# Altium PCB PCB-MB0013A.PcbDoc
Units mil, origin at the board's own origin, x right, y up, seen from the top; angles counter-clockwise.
Board outline 1190.03 x 715.03 mil, 2 copper layers (Top Layer, Bottom Layer); 10 components, 22 nets, 65 pads, 2 vias.
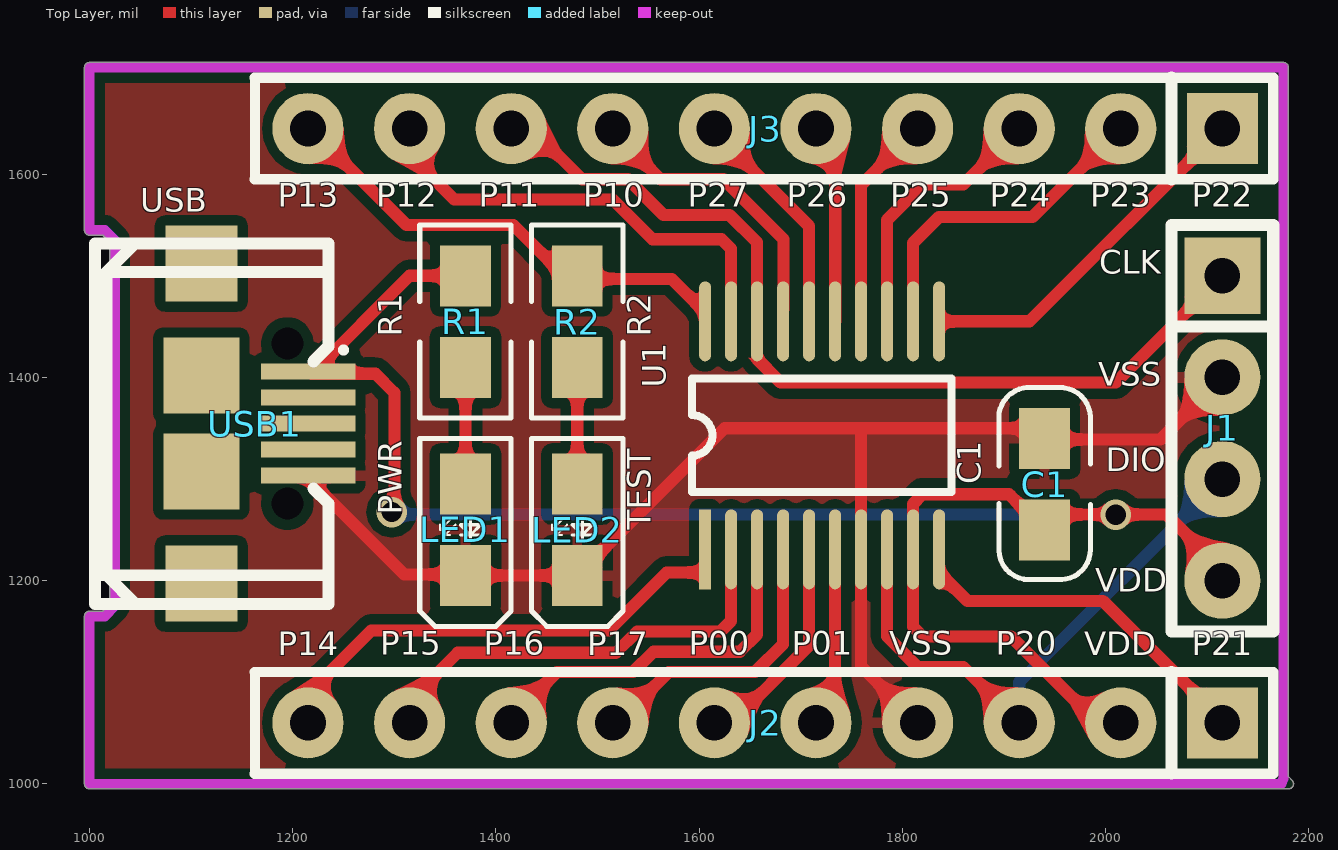
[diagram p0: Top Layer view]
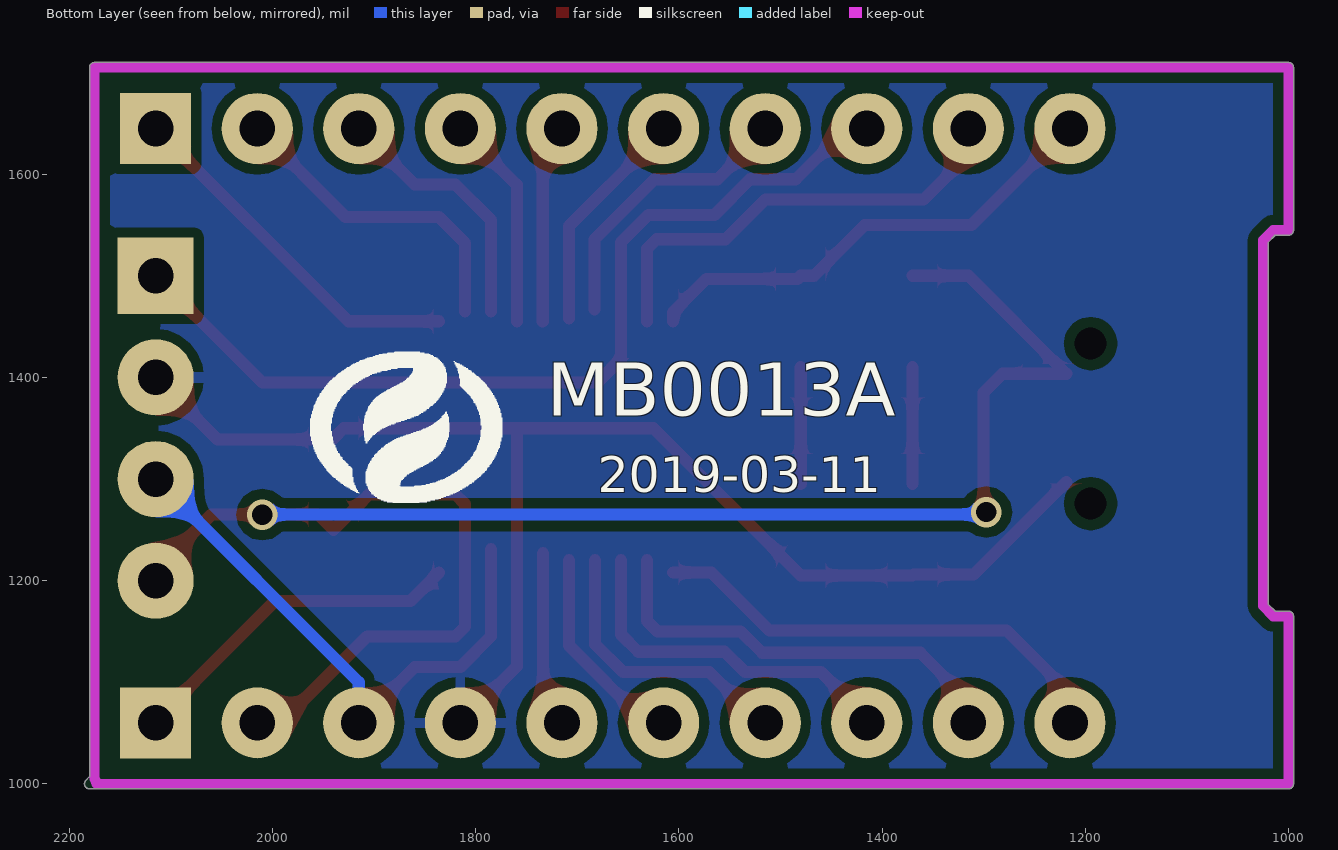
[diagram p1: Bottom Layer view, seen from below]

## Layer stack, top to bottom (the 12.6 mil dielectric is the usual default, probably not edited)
Top Solder: solder mask 0.4, Solder Resist, Dk 3.5
Top Layer: signal copper 1.4
Dielectric1: dielectric 12.6, FR-4, Dk 4.8
Bottom Layer: signal copper 1.4
Bottom Solder: solder mask 0.4, Solder Resist, Dk 3.5

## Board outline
1000,994.99 cw(c1000,1000) 994.99,1000 994.99,1165 cw(c1000,1165) 1000,1170.02 1012.92,1170.02 1019.99,1177.08 1019.99,1532.92 1012.92,1539.98 1000,1539.98 cw(c1000,1545) 994.99,1545 994.99,1705 cw(c1000,1705) 1000,1710.02 2175,1710.02 cw(c2175,1705) 2180.01,1705 2180.01,1007.08 2183.55,1003.55 2183.53,1003.56 cw(c2180,1000) 2185.01,1000 cw(c2180,1000) 2180,994.99

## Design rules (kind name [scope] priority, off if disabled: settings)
Clearance Clearance_2 [(InNamedPolygon('Top Layer-VSS'))] p1: gap=10 ignorepadtopadclearanceinfootprint=FALSE
Clearance Clearance_1 [(InNamedPolygon('Bottom Layer-VSS'))] p2: gap=10 ignorepadtopadclearanceinfootprint=FALSE
Clearance [(InComponent('USB1') AND InPadClass('All Pads')) vs (InPadClass('All Pads'))] p3: gap=1 ignorepadtopadclearanceinfootprint=FALSE except(0: Arc-Hole Track-Hole SMDPad-Hole THPad-Hole Via-Hole Fill-Hole Poly-Hole Region-Hole Text-Hole)
ComponentClearance [All] p1: gap=3 collisioncheckmode=3 verticalgap=3 showdistances=FALSE
FabricationTestpoint [(IsPad And (OnTopLayer Or OnBottomLayer))] p1: side=3 testpointundercomponent=TRUE minsize=40 maxsize=100 preferedsize=60 minholesize=0 maxholesize=40 preferedholesize=32 testpointgrid=1 allowsidetop=TRUE allowsidebottom=TRUE usegrid=TRUE gridtolerance=0.01
PolygonConnect [All] p1: connectstyle=Relief reliefconductorwidth=10 reliefentries=4 polygonreliefangle="90 Angle" airgapwidth=10
RoutingVias [All] p1: holewidth=20 width=30 viastyle="Through Hole" minholewidth=20 minwidth=30 maxholewidth=28 maxwidth=50
SolderMaskExpansion [All] p1: expansion=4
Width [All] p1: maxlimit=15 minlimit=3 preferedwidth=12
28 further rules are at their usual default settings.

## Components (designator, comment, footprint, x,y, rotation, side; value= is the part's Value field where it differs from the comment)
C1 "104" C0805 1940,1250 r90 top
J1 "烧录接口" CON1*4(P=2.54) 2115,1350 r270 top
J2 "CON1*10" CON1*10(P=2.54) 1665,1060 r180 top
J3 "CON1*10" CON1*10(P=2.54) 1665,1645 r180 top
LED1 "POWER" LED0805 1370,1250 r270 top
LED2 "TEST" LED0805 1480,1250 r270 top
R1 "1K" R0805 1370,1410 r90 top
R2 "1K" R0805 1480,1500 r270 top
U1 "SC92F8003" TSSOP20s 1721,1343 r90 top locked
USB1 "MicroUSB 供电口" microusb 1215.32,1405.7 r180 top

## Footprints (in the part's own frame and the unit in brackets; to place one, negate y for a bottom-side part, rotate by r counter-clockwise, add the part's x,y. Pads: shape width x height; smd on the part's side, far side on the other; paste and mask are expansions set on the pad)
C0805 [mil]
  rect 60x50 smd: 1(0,0) 2(90,0)
  silkscreen extent -49,-45 140,45
CON1*4(P=2.54) [mil]
  rect 75x75 hole 35: 1(-150,0)
  round 75 hole 35: 2(-50,0) 3(50,0) 4(150,0)
  silkscreen extent -200,-50 200,50
CON1*10(P=2.54) [mil]
  rect 70x70 hole 35: 1(-450,0)
  round 70 hole 35: 2(-350,0) 3(-250,0) 4(-150,0) 5(-50,0) 6(50,0) 7(150,0) 8(250,0) 9(350,0) 10(450,0)
  silkscreen extent -500,-50 502,50
LED0805 [mil]
  rect 60x50 smd: 1(-45,0) 2(45,0)
  silkscreen extent -90,-45 95,45
microusb [mm] "Connector; USB1.1, Type B, SM; 4 Position; Right Angle"
  rect 2.366x0.4 smd mask+0.001: 1(0,0) 2(0,0.65) 3(0,1.3) 4(0,1.95) 5(0,2.6)
  rect 1.8x1.9 smd: 6(2.675,-2.7) 9(2.675,5.3)
  rect 1.9x1.9 smd: 7(2.675,0.1) 8(2.675,2.5)
  round 0 hole 0.8 unplated mask+0.001: MH1(0.525,3.3) MH2(0.525,-0.7)
  silkscreen extent -0.89,-3.21 5.33,5.81, body extent -0.11,-3.09 5.52,5.71, height 2.79
R0805 [mil]
  rect 60x50 smd: 1(0,0) 2(90,0)
  silkscreen extent -50,-45 140,45
TSSOP20s [mm]
  rect 2x0.3 smd: 1(-2.85,2.925)
  oval 2x0.3 smd: 2(-2.85,2.275) 3(-2.85,1.625) 4(-2.85,0.975) 5(-2.85,0.325) 6(-2.85,-0.325) 7(-2.85,-0.975) 8(-2.85,-1.625) 9(-2.85,-2.275) 10(-2.85,-2.925) 11(2.85,-2.925) 12(2.85,-2.275) 13(2.85,-1.625) 14(2.85,-0.975) 15(2.85,-0.325) 16(2.85,0.325) 17(2.85,0.975) 18(2.85,1.625) 19(2.85,2.275) 20(2.85,2.925)
  silkscreen extent -1.41,-3.24 1.41,3.25

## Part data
C1: library part CAP1, "贴片电容"
J1: library part CON1*4
LED1 LED2: library part LED
R1 R2: library part R0805
U1: "电压:2.4V-5.5V;ROM:16KB;RAM:256B+256B;16/8/4/1.33MHz"
USB1: library part MicroUSB

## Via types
v1: diameter 30, hole 20, Top Layer to Bottom Layer, tented both sides, 2 vias

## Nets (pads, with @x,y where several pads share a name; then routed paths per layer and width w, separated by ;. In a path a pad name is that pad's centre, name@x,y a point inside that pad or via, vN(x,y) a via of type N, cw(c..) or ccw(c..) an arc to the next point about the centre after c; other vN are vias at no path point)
CLK: J1.1 J3.8 U1.18 | length 914.4
  Top Layer w12: J3.8 1435,1645 1485,1595 1530,1595 1565,1560 1630,1560 1656.87,1533.13 1656.87,1418.13 1680,1395 2010,1395 J1.1
DIO: J1.3 J2.3 U1.8 | length 573.9
  Top Layer w12: U1.8@1784.82,1230.8 1784.82,1145.18 1815,1115 1860,1115 J2.3
  Bottom Layer w12: J2.3 1915,1100 J1.3
NetLED1_1: LED1.1 R1.1 | length 115
  Top Layer w12: LED1.1 R1.1
NetLED2_1: LED2.1 R2.2 | length 115
  Top Layer w12: LED2.1 R2.2
P00: J2.6 U1.5 | length 208.5
  Top Layer w12: J2.6 1632,1060 1708.05,1136.05 U1.5@1708.05,1220
P01: J2.5 U1.6 | length 174.7
  Top Layer w12: J2.5 1733.64,1078.64 U1.6@1733.64,1227
P10: J3.7 U1.17 | length 265.4
  Top Layer w12: J3.7@1526,1631 1562,1595 1624,1595 1683,1536 U1.17@1683,1467
P12: J3.9 U1.19 | length 440.2
  Top Layer w12: J3.9@1305,1629 1359,1575 1515,1575 1554,1536 1622,1536 1631.28,1526.72 U1.19@1631.28,1455.2
P13: J3.10 R2.1 U1.20 | length 474.7
  Top Layer w12: J3.10 1217,1645 1312,1550 1417,1550 1467,1500 R2.1 1483,1497 1573,1497 1605.84,1464.16 U1.20
P14: J2.10 U1.1 | length 468.8
  Top Layer w12: J2.10 1215,1088.72 1277.28,1151 1511,1151 1568,1208 U1.1@1605.68,1208
P15: J2.9 U1.2 | length 430.2
  Top Layer w12: J2.9 1315,1081.64 1362.36,1129 1518,1129 1539,1150 1621,1150 1631.28,1160.28 U1.2@1631.28,1220
P16: J2.8 U1.3 | length 353.9
  Top Layer w12: J2.8 1415,1065 1460,1110 1535,1110 1555,1130 1640,1130 1656.87,1146.87 U1.3@1656.87,1220
P17: J2.7 U1.4 | length 260.1
  Top Layer w12: J2.7@1532,1072 1570,1110 1655,1110 1682.46,1137.46 U1.4@1682.46,1220
P21: J2.1 U1.10 | length 341.7
  Top Layer w12: U1.10@1836,1208 1864,1180 1997.36,1180 2115,1062.36 J2.1
P22: J3.1 U1.11 | length 357.5
  Top Layer w12: U1.11 1925.2,1455.2 J3.1
P23: J3.2 U1.12 | length 318.6
  Top Layer w12: U1.12@1810.41,1465 1810.41,1532.41 1836,1558 1928,1558 J3.2
P24: J3.3 U1.13 | length 257.3
  Top Layer w12: U1.13@1785,1465 1785,1555 1820,1590 1860,1590 J3.3
P25: J3.4 U1.14 | length 213.3
  Top Layer w12: U1.14@1759.23,1455.2 1759.23,1590 1760,1590 J3.4
P26: J3.5 U1.15 | length 197.7
  Top Layer w12: J3.5 1734,1626 U1.15@1734,1455.2
P27: J3.6 U1.16 | length 230
  Top Layer w12: J3.6@1603,1631 1626,1631 1708.05,1548.95 U1.16@1708.05,1458
VDD: C1.1 J1.4 J2.2 R1.2 U1.9 USB1.1 | length 1839
  Top Layer w12: v1(1297.5,1267.5) 1300,1270 1300,1385 1281.33,1403.67 1218.67,1403.67 1315,1500 R1.2 ; J2.2 1992,1060 1907,1145 1820,1145 1810.41,1154.59 1810.41,1275.41 1820,1285 1905,1285 C1.1 1955,1265 v1(2010,1265) 2060,1265 2115,1210 J1.4
  Bottom Layer w12: v1(1297.5,1267.5) 1300,1265 v1(2010,1265)
VSS: C1.2 J1.2 J2.4 LED1.2 LED2.2 U1.7 USB1.5 | length 1336.7
  Top Layer w12: USB1.5@1218.67,1297.08 1309.75,1206 1369,1206 LED1.2 LED2.2 1625,1350 1930,1350 C1.2 1941,1339 2054,1339 J1.2 ; 1759.23,1349.23 1759.23,1115.77 J2.4
pads on no net: USB1.2 USB1.3 USB1.4 USB1.6 USB1.7 USB1.8 USB1.9 USB1.MH1 USB1.MH2

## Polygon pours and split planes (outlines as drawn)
VSS on Bottom Layer "Bottom Layer-VSS" (solid, remove dead copper, pour order 4): 1000,1705 1000,1000 2172.93,1000 2175,1002.07 2175,1705
VSS on Top Layer "Top Layer-VSS" (solid, remove dead copper, pour order 6): 1000,1705 1000,1000 2172.93,1000 2172.93,1702.07 2170,1705

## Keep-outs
Keep-Out Layer:
  lines w10: 1000,1000 1000,1165 1015,1165 1025,1175 1025,1535 1015,1545 1000,1545 1000,1705 2175,1705 2175,1005 2172.93,1000 1000,1000

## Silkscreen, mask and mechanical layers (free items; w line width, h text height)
Top Overlay:
  text "P13" at 1185,1560 h40
  text "P12" at 1282,1560 h40
  text "P11" at 1383,1560 h40
  text "P10" at 1486,1560 h40
  text "P27" at 1589,1560 h40
  text "P26" at 1686,1560 h40
  text "P25" at 1788,1560 h40
  text "P24" at 1886,1560 h40
  text "P23" at 1985,1560 h40
  text "P22" at 2085,1560 h40
  text "USB" at 1050,1555 h40
  text "CLK" at 1994,1494 h40
  text "R1" at 1315,1440 h40 r90
  text "R2" at 1560,1440 h40 r90
  text "VSS" at 1992.64,1384 h40
  text "DIO" at 2000,1300 h40
  text "C1" at 1885,1295 h40 r90
  text "PWR" at 1315,1265 h40 r90
  text "TEST" at 1560,1250 h40 r90
  text "VDD" at 1989.71,1181 h40
  text "P14" at 1185,1118.67 h40
  text "P15" at 1286,1119 h40
  text "P16" at 1388,1119 h40
  text "P17" at 1490,1118.67 h40
  text "P00" at 1590,1119 h40
  text "P01" at 1691,1119 h40
  text "VSS" at 1787,1119 h40
  text "P20" at 1892,1119 h40
  text "VDD" at 1979,1118.67 h40
  text "P21" at 2085,1118.67 h40
Bottom Overlay:
  drawing of 987 lines, arcs and shapes, not listed
  text "MB0013A" at 1730,1345 h90
  text "2019-03-11" at 1680,1275 h60
Mechanical 1:
  lines w10: 1000,1000 2175,1000 2175,1705 1000,1705 1000,1545 1015,1545 1025,1535 1025,1175 1015,1165 1000,1165 1000,1000

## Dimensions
2175,1705 to 2175,1000 on Mechanical 1
1000,1705 to 2175,1705 on Mechanical 1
